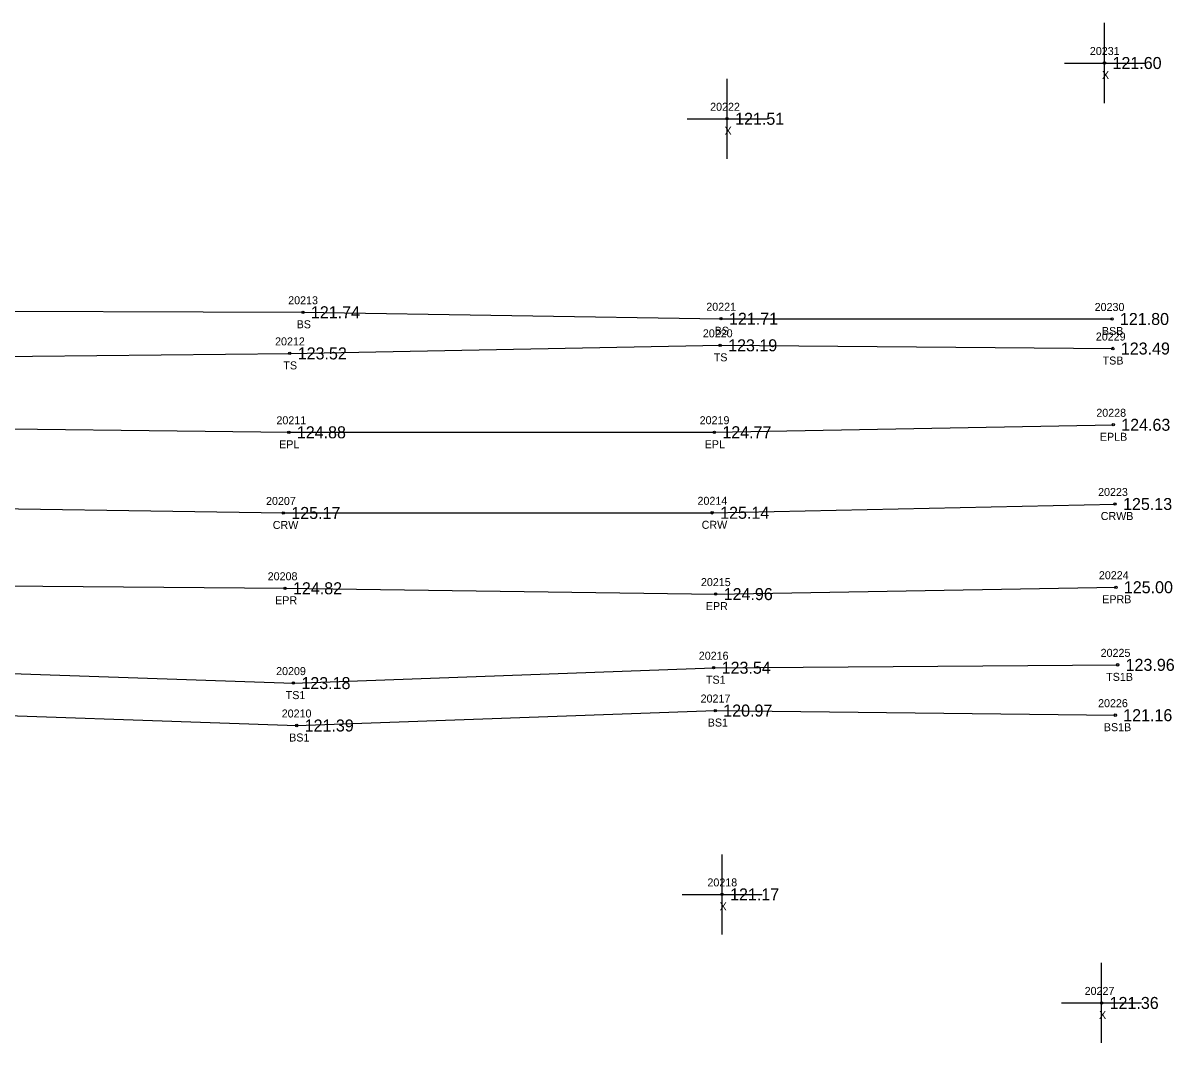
# Model space of a CAD drawing. Extents: x 2375812 to 2377225, y 1024470 to 1025135.
# Drawn here: x 2377080.8 to 2377224.7, y 1024853.9 to 1024981.3 of the extents above; entities that cross this region are included whole.
import ezdxf

# ---------------------------------------------------------------- set-up
doc = ezdxf.new("R2010")
doc.units = 0
for name, color, linetype in [('RD_DTM_BkLn1', 7, 'Continuous'), ('RD_DTM_BkLn2', 7, 'Continuous'), ('RD_DTM_BkLn_txCode', 7, 'Continuous'), ('RD_EX_Misc', 7, 'Continuous'), ('RD_EX_Misc_txCode', 7, 'Continuous'), ('RD_EX_Road', 7, 'Continuous'), ('RD_EX_Road_txCode', 7, 'Continuous'), ('RD_EX_TX_Misc_ELEV', 7, 'Continuous'), ('RD_EX_TX_Road_ELEV', 7, 'Continuous'), ('RD_HC_Survey_ELEV', 7, 'Continuous'), ('RD_HC_Survey_txCode', 7, 'Continuous'), ('RD_SMD_Locator', 7, 'Continuous')]:
    doc.layers.add(name, color=color, linetype=linetype)

msp = doc.modelspace()

# ---------------------------------------------------------------- linework, layer by layer
at = {"layer": 'RD_DTM_BkLn1'}
msp.add_lwpolyline([(2376561.75, 1024926.35), (2376659.86, 1024925.07), (2376762.41, 1024923.95), (2376865.76, 1024922.65), (2376965.3, 1024921.9), (2377063.64, 1024920.86), (2377113.34, 1024920.1), (2377166.94, 1024920.12), (2377217.3, 1024921.22)], dxfattribs=at)
at = {"layer": 'RD_DTM_BkLn2'}
for points in [[(2376538.09, 1024944), (2376550.49, 1024951.37), (2376563.43, 1024953.34), (2376659.84, 1024952.77), (2376765.68, 1024950.71), (2376864.8, 1024951), (2376966.18, 1024947.81), (2377065.88, 1024945.38), (2377115.79, 1024945.18), (2377168.04, 1024944.37), (2377216.91, 1024944.34)], [(2376561.81, 1024938.95), (2376565.65, 1024944.33), (2376658.56, 1024947.18), (2376764.14, 1024946.5), (2376864.38, 1024942.41), (2376965.82, 1024942.74), (2377065.85, 1024939.54), (2377114.14, 1024940.04), (2377167.94, 1024941.05), (2377217.02, 1024940.65)], [(2376561.53, 1024913.62), (2376561.38, 1024909.35), (2376658.21, 1024899.77), (2376672.96, 1024897.91), (2376688.03, 1024903.17), (2376760.99, 1024901.04), (2376828.16, 1024902.22), (2376853.81, 1024902.74), (2376860.1, 1024898.86), (2376865.34, 1024899.92), (2376875.73, 1024904.61), (2376896.78, 1024904.73), (2376899.24, 1024901.87), (2376965.55, 1024899.2), (2377063.48, 1024900.56), (2377114.6, 1024898.84), (2377167.13, 1024900.76), (2377217.62, 1024901.12)], [(2376543.21, 1024910.85), (2376558.6, 1024896.28), (2376588.49, 1024894.01), (2376656.25, 1024894.1), (2376679.22, 1024888.45), (2376688.36, 1024892.22), (2376760.25, 1024888.88), (2376862.95, 1024889.28), (2376867.73, 1024890.58), (2376879.38, 1024883.12), (2376893.75, 1024882.89), (2376900.24, 1024892.67), (2376965.04, 1024891.16), (2377064.46, 1024895.27), (2377115.01, 1024893.54), (2377167.33, 1024895.41), (2377217.32, 1024894.83)]]:
    msp.add_lwpolyline(points, dxfattribs=at)
at = {"layer": 'RD_EX_Misc'}
for p, q in [((2377215.98, 1024971.33), (2377215.98, 1024981.33)), ((2377210.98, 1024976.33), (2377220.98, 1024976.33)), ((2377168.81, 1024964.36), (2377168.81, 1024974.36)), ((2377163.81, 1024969.36), (2377173.81, 1024969.36)), ((2377168.18, 1024867.43), (2377168.18, 1024877.43)), ((2377163.18, 1024872.43), (2377173.18, 1024872.43)), ((2377215.62, 1024853.87), (2377215.62, 1024863.87)), ((2377210.62, 1024858.87), (2377220.62, 1024858.87))]:
    msp.add_line(p, q, dxfattribs=at)
at = {"layer": 'RD_EX_Road'}
for points in [[(2376561.85, 1024938.22), (2376659.62, 1024935.3), (2376763.51, 1024933.89), (2376865.73, 1024932.88), (2376965.35, 1024932.49), (2377065.13, 1024930.78), (2377114.03, 1024930.18), (2377167.22, 1024930.19), (2377217.07, 1024931.12)], [(2376561.38, 1024915.36), (2376658.71, 1024915.48), (2376761.9, 1024913.76), (2376865.54, 1024912.46), (2376965.34, 1024911.98), (2377063.07, 1024911.1), (2377113.55, 1024910.69), (2377167.38, 1024909.96), (2377217.4, 1024910.82)]]:
    msp.add_lwpolyline(points, dxfattribs=at)
at = {"layer": 'RD_SMD_Locator'}
for centre in [(2377215.98, 1024976.33), (2377168.81, 1024969.36), (2377115.79, 1024945.18), (2377168.04, 1024944.37), (2377216.91, 1024944.34), (2377167.94, 1024941.05), (2377114.14, 1024940.04), (2377217.02, 1024940.65), (2377217.07, 1024931.12), (2377114.03, 1024930.18), (2377167.22, 1024930.19), (2377217.3, 1024921.22), (2377113.34, 1024920.1), (2377166.94, 1024920.12), (2377113.55, 1024910.69), (2377217.4, 1024910.82), (2377167.38, 1024909.96), (2377167.13, 1024900.76), (2377217.62, 1024901.12), (2377114.6, 1024898.84), (2377167.33, 1024895.41), (2377217.32, 1024894.83), (2377115.01, 1024893.54), (2377168.18, 1024872.43), (2377215.62, 1024858.87)]:
    msp.add_circle(centre, 0.15, dxfattribs=at)

# ---------------------------------------------------------------- texts
at = {"layer": 'RD_DTM_BkLn_txCode'}
for s, p in [('20213', (2377113.95, 1024946.18)), ('20221', (2377166.21, 1024945.37)), ('20230', (2377214.75, 1024945.34)), ('BS', (2377115.01, 1024943.18)), ('20220', (2377165.78, 1024942.05)), ('BS', (2377167.26, 1024942.37)), ('20229', (2377214.9, 1024941.65)), ('BSB', (2377215.66, 1024942.34)), ('20212', (2377112.31, 1024941.04)), ('TS', (2377167.14, 1024939.05)), ('TSB', (2377215.75, 1024938.65)), ('TS', (2377113.35, 1024938.04)), ('20216', (2377165.27, 1024901.76)), ('20225', (2377215.5, 1024902.12)), ('20209', (2377112.44, 1024899.84)), ('TS1', (2377166.17, 1024898.76)), ('TS1B', (2377216.19, 1024899.12)), ('TS1', (2377113.64, 1024896.84)), ('20217', (2377165.5, 1024896.41)), ('20226', (2377215.18, 1024895.83)), ('20210', (2377113.14, 1024894.54)), ('BS1', (2377166.39, 1024893.41)), ('BS1B', (2377215.9, 1024892.83)), ('BS1', (2377114.07, 1024891.54))]:
    msp.add_text(s, height=1, dxfattribs=at).set_placement(p)
at = {"layer": 'RD_EX_Misc_txCode'}
for s, p in [('20231', (2377214.15, 1024977.33)), ('X', (2377215.67, 1024974.33)), ('20222', (2377166.69, 1024970.36)), ('X', (2377168.49, 1024967.36)), ('20218', (2377166.35, 1024873.43)), ('X', (2377167.87, 1024870.43)), ('20227', (2377213.5, 1024859.87)), ('X', (2377215.3, 1024856.87))]:
    msp.add_text(s, height=1, dxfattribs=at).set_placement(p)
at = {"layer": 'RD_EX_Road_txCode'}
for s, p in [('20228', (2377214.96, 1024932.12)), ('20211', (2377112.48, 1024931.18)), ('20219', (2377165.38, 1024931.19)), ('EPLB', (2377215.4, 1024929.12)), ('EPL', (2377112.82, 1024928.18)), ('EPL', (2377166.01, 1024928.19)), ('20208', (2377111.39, 1024911.69)), ('20224', (2377215.28, 1024911.82)), ('20215', (2377165.54, 1024910.96)), ('EPR', (2377112.32, 1024908.69)), ('EPRB', (2377215.7, 1024908.82)), ('EPR', (2377166.15, 1024907.96))]:
    msp.add_text(s, height=1, dxfattribs=at).set_placement(p)
at = {"layer": 'RD_EX_TX_Misc_ELEV'}
for s, p in [('121.60', (2377216.98, 1024975.58)), ('121.51', (2377169.81, 1024968.61)), ('121.74', (2377116.79, 1024944.43)), ('121.71', (2377169.04, 1024943.62)), ('121.80', (2377217.91, 1024943.59)), ('123.19', (2377168.94, 1024940.3)), ('123.49', (2377218.02, 1024939.9)), ('123.52', (2377115.14, 1024939.29)), ('123.54', (2377168.13, 1024900.01)), ('123.96', (2377218.62, 1024900.37)), ('123.18', (2377115.6, 1024898.09)), ('120.97', (2377168.33, 1024894.66)), ('121.16', (2377218.32, 1024894.08)), ('121.39', (2377116.01, 1024892.79)), ('121.17', (2377169.18, 1024871.68)), ('121.36', (2377216.62, 1024858.12))]:
    msp.add_text(s, height=1.5, dxfattribs=at).set_placement(p)
at = {"layer": 'RD_EX_TX_Road_ELEV'}
for s, p in [('124.88', (2377115.03, 1024929.43)), ('124.77', (2377168.22, 1024929.44)), ('124.63', (2377218.07, 1024930.37)), ('124.82', (2377114.55, 1024909.94)), ('124.96', (2377168.38, 1024909.21)), ('125.00', (2377218.4, 1024910.07))]:
    msp.add_text(s, height=1.5, dxfattribs=at).set_placement(p)
at = {"layer": 'RD_HC_Survey_ELEV'}
for s, p in [('125.17', (2377114.34, 1024919.35)), ('125.14', (2377167.94, 1024919.37)), ('125.13', (2377218.3, 1024920.47))]:
    msp.add_text(s, height=1.5, dxfattribs=at).set_placement(p)
at = {"layer": 'RD_HC_Survey_txCode'}
for s, p in [('20223', (2377215.18, 1024922.22)), ('20207', (2377111.18, 1024921.1)), ('20214', (2377165.11, 1024921.12)), ('CRWB', (2377215.51, 1024919.22)), ('CRW', (2377112.02, 1024918.1)), ('CRW', (2377165.63, 1024918.12))]:
    msp.add_text(s, height=1, dxfattribs=at).set_placement(p)

doc.saveas('drawing.dxf')
